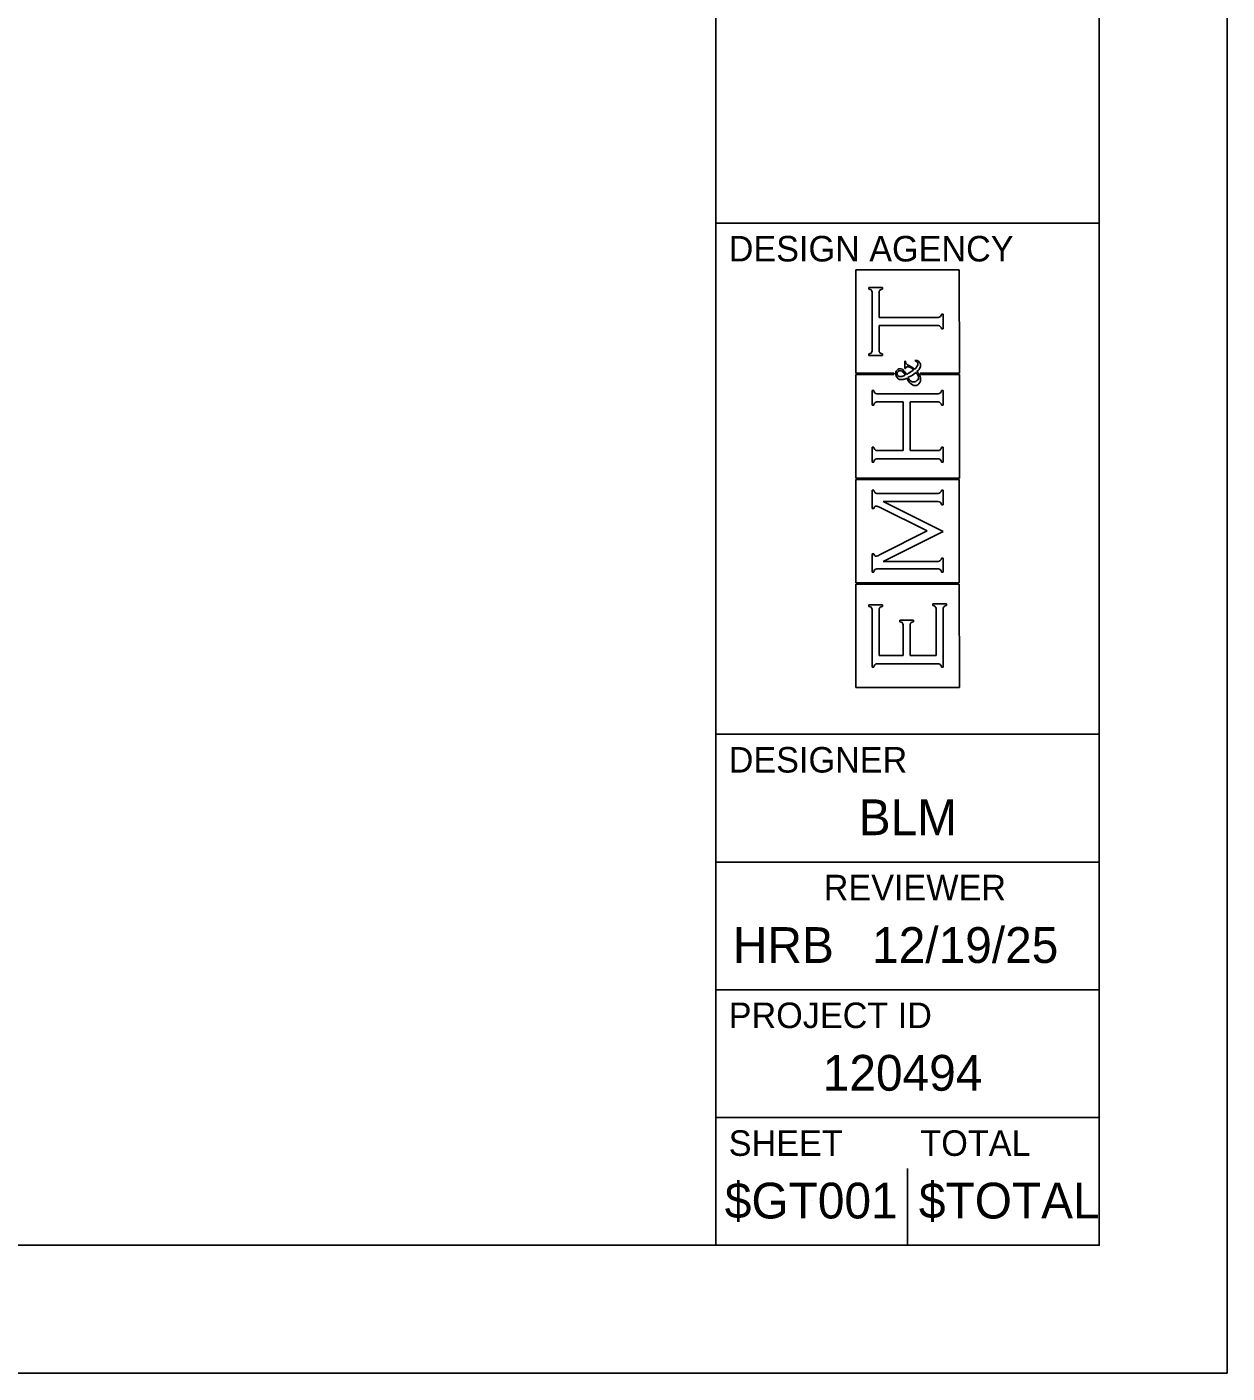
# Model space of a CAD drawing. Extents: x -7.1 to 34, y 0 to 22.
# Drawn here: x 29.3 to 34, y 0 to 5.27 of the extents above; entities that cross this region are included whole.
import ezdxf

# ---------------------------------------------------------------- set-up
doc = ezdxf.new("R2010")
doc.units = 0
for name, color, linetype in [('SH_Border', 7, 'Continuous'), ('SH_Cut_Line', 7, 'Continuous'), ('SH_Data', 7, 'Continuous')]:
    doc.layers.add(name, color=color, linetype=linetype)

msp = doc.modelspace()

# ---------------------------------------------------------------- linework, layer by layer
at = {"layer": 'SH_Border'}
for p, q in [((32, 0.5), (32, 21.5)), ((32, 4.5), (33.5, 4.5)), ((32, 2.5), (33.5, 2.5)), ((32, 2), (33.5, 2)), ((32, 1.5), (33.5, 1.5)), ((32, 1), (33.5, 1))]:
    msp.add_line(p, q, dxfattribs=at)
msp.add_lwpolyline([(1.5, 21.5), (33.5, 21.5), (33.5, 0.5), (1.5, 0.5)], close=True, dxfattribs=at)
at = {"layer": 'SH_Cut_Line'}
msp.add_lwpolyline([(0, 0), (34, 0), (34, 22), (0, 22)], close=True, dxfattribs=at)
at = {"layer": 'SH_Data'}
for p, q in [((32.9523, 4.3174), (32.5477, 4.3174)), ((32.5477, 4.3174), (32.5477, 3.9128)), ((32.9524, 3.9128), (32.9523, 4.3174)), ((32.5984, 4.2421), (32.5984, 4.2486)), ((32.5984, 4.2486), (32.6511, 4.2486)), ((32.6036, 4.2408), (32.5984, 4.2421)), ((32.6071, 4.2391), (32.6036, 4.2408)), ((32.6088, 4.2367), (32.6071, 4.2391)), ((32.6106, 4.2343), (32.6088, 4.2367)), ((32.6114, 4.2303), (32.6106, 4.2343)), ((32.6114, 4.2246), (32.6114, 4.2303)), ((32.6114, 4.0055), (32.6114, 4.2246)), ((32.639, 4.2343), (32.6381, 4.2303)), ((32.6381, 4.2303), (32.6381, 4.2246)), ((32.6381, 4.2246), (32.6381, 4.1309)), ((32.6407, 4.2367), (32.639, 4.2343)), ((32.6424, 4.2391), (32.6407, 4.2367)), ((32.6459, 4.2409), (32.6424, 4.2391)), ((32.6511, 4.2421), (32.6459, 4.2409)), ((32.6511, 4.2486), (32.6511, 4.2421)), ((32.6381, 4.1309), (32.8646, 4.1309)), ((32.8646, 4.1309), (32.8701, 4.1309)), ((32.8701, 4.1309), (32.8741, 4.1318)), ((32.8741, 4.1318), (32.8765, 4.1336)), ((32.8765, 4.1336), (32.8788, 4.1353)), ((32.8788, 4.1353), (32.8807, 4.1388)), ((32.8807, 4.1388), (32.882, 4.1439)), ((32.882, 4.1439), (32.8885, 4.1439)), ((32.8885, 4.1439), (32.8885, 4.0862)), ((32.8646, 4.0992), (32.6381, 4.0992)), ((32.6381, 4.0992), (32.6381, 4.0055)), ((32.8703, 4.0992), (32.8646, 4.0992)), ((32.8743, 4.0983), (32.8703, 4.0992)), ((32.8766, 4.0966), (32.8743, 4.0983)), ((32.8789, 4.0948), (32.8766, 4.0966)), ((32.8807, 4.0914), (32.8789, 4.0948)), ((32.882, 4.0862), (32.8807, 4.0914)), ((32.8885, 4.0862), (32.882, 4.0862)), ((32.6114, 3.9998), (32.6114, 4.0055)), ((32.6381, 4.0055), (32.6381, 3.9998)), ((32.5984, 3.9881), (32.6036, 3.9893)), ((32.5984, 3.9816), (32.5984, 3.9881)), ((32.6511, 3.9816), (32.5984, 3.9816)), ((32.6036, 3.9893), (32.6071, 3.9911)), ((32.6071, 3.9911), (32.6088, 3.9934)), ((32.6088, 3.9934), (32.6106, 3.9958)), ((32.6106, 3.9958), (32.6114, 3.9998)), ((32.6381, 3.9998), (32.639, 3.9958)), ((32.639, 3.9958), (32.6407, 3.9934)), ((32.6407, 3.9934), (32.6424, 3.9911)), ((32.6424, 3.9911), (32.6459, 3.9893)), ((32.6459, 3.9893), (32.6511, 3.9881)), ((32.6511, 3.9881), (32.6511, 3.9816)), ((32.739, 3.9311), (32.739, 3.9596)), ((32.739, 3.9596), (32.7415, 3.9596)), ((32.7415, 3.9596), (32.7418, 3.9556)), ((32.7418, 3.9556), (32.7427, 3.9527)), ((32.7427, 3.9527), (32.7441, 3.9508)), ((32.7794, 3.9612), (32.7813, 3.9637)), ((32.7827, 3.9603), (32.7794, 3.9612)), ((32.7813, 3.9637), (32.7877, 3.9621)), ((32.7852, 3.9588), (32.7827, 3.9603)), ((32.7869, 3.9566), (32.7852, 3.9588)), ((32.7886, 3.9545), (32.7869, 3.9566)), ((32.7877, 3.9621), (32.7924, 3.9594)), ((32.7895, 3.9518), (32.7886, 3.9545)), ((32.7895, 3.9487), (32.7895, 3.9518)), ((32.7924, 3.9594), (32.7955, 3.9557)), ((32.7955, 3.9557), (32.7986, 3.952)), ((32.7986, 3.952), (32.8001, 3.9477)), ((32.5477, 3.9128), (32.6968, 3.9128)), ((32.6963, 3.9073), (32.5477, 3.9073)), ((32.5477, 3.9073), (32.5477, 3.5027)), ((32.6968, 3.9128), (32.6963, 3.9073)), ((32.7041, 3.9168), (32.7057, 3.9211)), ((32.7041, 3.9114), (32.7041, 3.9168)), ((32.7041, 3.9058), (32.7041, 3.9114)), ((32.7057, 3.9007), (32.7041, 3.9058)), ((32.7057, 3.9211), (32.7089, 3.9245)), ((32.7089, 3.8963), (32.7057, 3.9007)), ((32.7089, 3.9245), (32.7121, 3.9279)), ((32.7101, 3.9167), (32.709, 3.9142)), ((32.709, 3.9142), (32.709, 3.9112)), ((32.709, 3.9112), (32.709, 3.9073)), ((32.709, 3.9073), (32.7104, 3.9043)), ((32.7122, 3.9187), (32.7101, 3.9167)), ((32.7104, 3.9043), (32.7131, 3.9023)), ((32.7121, 3.9279), (32.716, 3.9296)), ((32.7143, 3.9207), (32.7122, 3.9187)), ((32.7131, 3.9023), (32.7159, 3.9003)), ((32.717, 3.9217), (32.7143, 3.9207)), ((32.7159, 3.9003), (32.7185, 3.8993)), ((32.716, 3.9296), (32.7206, 3.9296)), ((32.7203, 3.9217), (32.717, 3.9217)), ((32.7185, 3.8993), (32.7212, 3.8993)), ((32.7245, 3.9217), (32.7203, 3.9217)), ((32.7206, 3.9296), (32.7254, 3.9296)), ((32.7212, 3.8993), (32.7234, 3.8993)), ((32.7234, 3.8993), (32.7259, 3.8997)), ((32.7282, 3.9203), (32.7245, 3.9217)), ((32.7254, 3.9296), (32.7296, 3.928)), ((32.7259, 3.8997), (32.7286, 3.9004)), ((32.7316, 3.9175), (32.7282, 3.9203)), ((32.7286, 3.9004), (32.7314, 3.9012)), ((32.7296, 3.928), (32.7332, 3.9247)), ((32.7314, 3.9012), (32.7354, 3.9026)), ((32.735, 3.9147), (32.7316, 3.9175)), ((32.7332, 3.9247), (32.7368, 3.9213)), ((32.7381, 3.9104), (32.735, 3.9147)), ((32.7354, 3.9026), (32.7407, 3.9048)), ((32.7368, 3.9213), (32.7407, 3.9155)), ((32.7407, 3.9048), (32.7381, 3.9104)), ((32.7415, 3.9311), (32.739, 3.9311)), ((32.7407, 3.9155), (32.745, 3.9071)), ((32.7417, 3.9329), (32.7415, 3.9311)), ((32.7424, 3.9343), (32.7417, 3.9329)), ((32.7436, 3.9353), (32.7424, 3.9343)), ((32.7452, 3.9367), (32.7436, 3.9353)), ((32.7441, 3.9508), (32.7455, 3.949)), ((32.745, 3.9071), (32.7551, 3.913)), ((32.7471, 3.9374), (32.7452, 3.9367)), ((32.7455, 3.949), (32.7498, 3.946)), ((32.7491, 3.9374), (32.7471, 3.9374)), ((32.7556, 3.9374), (32.7491, 3.9374)), ((32.7498, 3.946), (32.7569, 3.942)), ((32.7551, 3.913), (32.7645, 3.9191)), ((32.7635, 3.9334), (32.7556, 3.9374)), ((32.7614, 3.9008), (32.7567, 3.8982)), ((32.7569, 3.942), (32.764, 3.938)), ((32.7651, 3.9031), (32.7614, 3.9008)), ((32.773, 3.9253), (32.7635, 3.9334)), ((32.764, 3.938), (32.7707, 3.9335)), ((32.7645, 3.9191), (32.773, 3.9253)), ((32.7688, 3.9054), (32.7651, 3.9031)), ((32.7747, 3.9096), (32.7688, 3.9054)), ((32.7707, 3.9335), (32.7769, 3.9285)), ((32.7828, 3.9155), (32.7747, 3.9096)), ((32.7769, 3.9285), (32.7816, 3.9325)), ((32.7816, 3.9325), (32.7848, 3.9361)), ((32.7866, 3.911), (32.7828, 3.9155)), ((32.7848, 3.9361), (32.7867, 3.9392)), ((32.7891, 3.9074), (32.7866, 3.911)), ((32.7867, 3.9392), (32.7885, 3.9424)), ((32.7916, 3.9236), (32.7867, 3.9191)), ((32.7867, 3.9191), (32.7917, 3.9135)), ((32.7885, 3.9424), (32.7895, 3.9455)), ((32.7902, 3.9048), (32.7891, 3.9074)), ((32.7895, 3.9455), (32.7895, 3.9487)), ((32.7914, 3.9021), (32.7902, 3.9048)), ((32.792, 3.8994), (32.7914, 3.9021)), ((32.795, 3.9277), (32.7916, 3.9236)), ((32.7917, 3.9135), (32.7952, 3.9084)), ((32.792, 3.8965), (32.792, 3.8994)), ((32.797, 3.9315), (32.795, 3.9277)), ((32.7952, 3.9084), (32.7972, 3.9039)), ((32.7991, 3.9353), (32.797, 3.9315)), ((32.7972, 3.9039), (32.7991, 3.8994)), ((32.8001, 3.9391), (32.7991, 3.9353)), ((32.7991, 3.8994), (32.8001, 3.8946)), ((32.8036, 3.9073), (32.7997, 3.9128)), ((32.7997, 3.9128), (32.9524, 3.9128)), ((32.8001, 3.9477), (32.8001, 3.9428)), ((32.8001, 3.9428), (32.8001, 3.9391)), ((32.9524, 3.9073), (32.8036, 3.9073)), ((32.9524, 3.5027), (32.9524, 3.9073)), ((32.7129, 3.8906), (32.7089, 3.8963)), ((32.7188, 3.8878), (32.7129, 3.8906)), ((32.7265, 3.8878), (32.7188, 3.8878)), ((32.7293, 3.8878), (32.7265, 3.8878)), ((32.7322, 3.8881), (32.7293, 3.8878)), ((32.7352, 3.8889), (32.7322, 3.8881)), ((32.7382, 3.8897), (32.7352, 3.8889)), ((32.742, 3.8911), (32.7382, 3.8897)), ((32.7467, 3.8932), (32.742, 3.8911)), ((32.7525, 3.8824), (32.7467, 3.8932)), ((32.7567, 3.8982), (32.7512, 3.8954)), ((32.7512, 3.8954), (32.7543, 3.8901)), ((32.7582, 3.875), (32.7525, 3.8824)), ((32.7543, 3.8901), (32.7578, 3.8861)), ((32.7578, 3.8861), (32.7615, 3.8833)), ((32.7636, 3.8711), (32.7582, 3.875)), ((32.7615, 3.8833), (32.7653, 3.8806)), ((32.769, 3.8672), (32.7636, 3.8711)), ((32.7653, 3.8806), (32.7694, 3.8793)), ((32.7745, 3.8652), (32.769, 3.8672)), ((32.7694, 3.8793), (32.7737, 3.8793)), ((32.7737, 3.8793), (32.7786, 3.8793)), ((32.7799, 3.8652), (32.7745, 3.8652)), ((32.7786, 3.8793), (32.7828, 3.8808)), ((32.7854, 3.8652), (32.7799, 3.8652)), ((32.7828, 3.8808), (32.7865, 3.8839)), ((32.7902, 3.8674), (32.7854, 3.8652)), ((32.7865, 3.8839), (32.7902, 3.8871)), ((32.7902, 3.8871), (32.792, 3.8913)), ((32.7942, 3.8718), (32.7902, 3.8674)), ((32.792, 3.8913), (32.792, 3.8965)), ((32.7981, 3.8762), (32.7942, 3.8718)), ((32.8001, 3.8821), (32.7981, 3.8762)), ((32.8001, 3.8946), (32.8001, 3.8895)), ((32.8001, 3.8895), (32.8001, 3.8821)), ((32.6114, 3.7873), (32.6114, 3.845)), ((32.6114, 3.845), (32.6179, 3.845)), ((32.6179, 3.845), (32.6193, 3.8399)), ((32.621, 3.7959), (32.6192, 3.7924)), ((32.6193, 3.8399), (32.6211, 3.8364)), ((32.6233, 3.7976), (32.621, 3.7959)), ((32.6211, 3.8364), (32.6234, 3.8347)), ((32.6257, 3.7994), (32.6233, 3.7976)), ((32.6234, 3.8347), (32.6257, 3.8329)), ((32.6257, 3.8329), (32.6297, 3.832)), ((32.6297, 3.8003), (32.6257, 3.7994)), ((32.6297, 3.832), (32.6354, 3.832)), ((32.6354, 3.8003), (32.6297, 3.8003)), ((32.6354, 3.832), (32.8646, 3.832)), ((32.7327, 3.8003), (32.6354, 3.8003)), ((32.7327, 3.6098), (32.7327, 3.8003)), ((32.8646, 3.8003), (32.7594, 3.8003)), ((32.7594, 3.8003), (32.7594, 3.6098)), ((32.8646, 3.832), (32.8701, 3.832)), ((32.8703, 3.8003), (32.8646, 3.8003)), ((32.8701, 3.832), (32.8741, 3.8329)), ((32.8743, 3.7994), (32.8703, 3.8003)), ((32.8741, 3.8329), (32.8765, 3.8347)), ((32.8766, 3.7976), (32.8743, 3.7994)), ((32.8765, 3.8347), (32.8788, 3.8364)), ((32.8789, 3.7959), (32.8766, 3.7976)), ((32.8788, 3.8364), (32.8807, 3.8399)), ((32.8807, 3.7924), (32.8789, 3.7959)), ((32.8807, 3.8399), (32.882, 3.845)), ((32.882, 3.845), (32.8885, 3.845)), ((32.8885, 3.845), (32.8885, 3.7873)), ((32.6179, 3.7873), (32.6114, 3.7873)), ((32.6192, 3.7924), (32.6179, 3.7873)), ((32.882, 3.7873), (32.8807, 3.7924)), ((32.8885, 3.7873), (32.882, 3.7873)), ((32.6115, 3.565), (32.6115, 3.6228)), ((32.6115, 3.6228), (32.6179, 3.6228)), ((32.6179, 3.6228), (32.6193, 3.6176)), ((32.6193, 3.6176), (32.6211, 3.6142)), ((32.6211, 3.6142), (32.6234, 3.6124)), ((32.6234, 3.6124), (32.6257, 3.6107)), ((32.6257, 3.6107), (32.6297, 3.6098)), ((32.6297, 3.6098), (32.6354, 3.6098)), ((32.6354, 3.6098), (32.7327, 3.6098)), ((32.7594, 3.6098), (32.8646, 3.6098)), ((32.8646, 3.6098), (32.8703, 3.6098)), ((32.8703, 3.6098), (32.8743, 3.6106)), ((32.8743, 3.6106), (32.8766, 3.6123)), ((32.8766, 3.6123), (32.8789, 3.614)), ((32.8789, 3.614), (32.8807, 3.6175)), ((32.8807, 3.6175), (32.882, 3.6228)), ((32.882, 3.6228), (32.8885, 3.6228)), ((32.8885, 3.6228), (32.8885, 3.565)), ((32.6179, 3.565), (32.6115, 3.565)), ((32.6192, 3.5702), (32.6179, 3.565)), ((32.621, 3.5736), (32.6192, 3.5702)), ((32.6233, 3.5754), (32.621, 3.5736)), ((32.6257, 3.5771), (32.6233, 3.5754)), ((32.6297, 3.578), (32.6257, 3.5771)), ((32.6354, 3.578), (32.6297, 3.578)), ((32.8646, 3.578), (32.6354, 3.578)), ((32.8703, 3.578), (32.8646, 3.578)), ((32.8743, 3.5772), (32.8703, 3.578)), ((32.8766, 3.5755), (32.8743, 3.5772)), ((32.8789, 3.5738), (32.8766, 3.5755)), ((32.8807, 3.5703), (32.8789, 3.5738)), ((32.882, 3.565), (32.8807, 3.5703)), ((32.8885, 3.565), (32.882, 3.565)), ((32.5477, 3.5027), (32.9524, 3.5027)), ((32.9523, 3.4973), (32.5477, 3.4973)), ((32.5477, 3.4973), (32.5477, 3.0927)), ((32.75, 3.5), (32.75, 3.5)), ((32.9523, 3.0927), (32.9523, 3.4973)), ((32.6115, 3.3831), (32.6115, 3.4555)), ((32.6115, 3.4555), (32.6179, 3.4555)), ((32.6179, 3.4555), (32.6193, 3.4504)), ((32.6193, 3.4504), (32.6211, 3.4469)), ((32.6211, 3.4469), (32.6234, 3.4452)), ((32.6234, 3.4452), (32.6257, 3.4434)), ((32.6257, 3.4434), (32.6297, 3.4425)), ((32.6297, 3.4425), (32.6354, 3.4425)), ((32.6354, 3.4425), (32.8646, 3.4425)), ((32.8646, 3.4425), (32.8701, 3.4425)), ((32.8701, 3.4425), (32.8741, 3.4434)), ((32.8741, 3.4434), (32.8765, 3.4452)), ((32.8765, 3.4452), (32.8788, 3.4469)), ((32.8788, 3.4469), (32.8807, 3.4504)), ((32.8807, 3.4504), (32.882, 3.4555)), ((32.882, 3.4555), (32.8885, 3.4555)), ((32.8885, 3.4555), (32.8885, 3.3978)), ((32.6179, 3.3831), (32.6115, 3.3831)), ((32.6202, 3.3897), (32.6179, 3.3831)), ((32.6232, 3.3931), (32.6202, 3.3897)), ((32.6267, 3.3931), (32.6232, 3.3931)), ((32.6294, 3.3931), (32.6267, 3.3931)), ((32.634, 3.3914), (32.6294, 3.3931)), ((32.6405, 3.3882), (32.634, 3.3914)), ((32.8259, 3.2954), (32.6405, 3.3882)), ((32.8645, 3.4108), (32.6549, 3.4108)), ((32.6549, 3.4108), (32.8885, 3.2928)), ((32.8702, 3.4108), (32.8645, 3.4108)), ((32.8742, 3.4099), (32.8702, 3.4108)), ((32.8765, 3.4082), (32.8742, 3.4099)), ((32.8789, 3.4066), (32.8765, 3.4082)), ((32.8807, 3.4031), (32.8789, 3.4066)), ((32.882, 3.3978), (32.8807, 3.4031)), ((32.8885, 3.3978), (32.882, 3.3978)), ((32.6421, 3.2029), (32.8259, 3.2954)), ((32.8885, 3.2928), (32.6549, 3.1763)), ((32.6115, 3.1344), (32.6115, 3.2062)), ((32.6115, 3.2062), (32.6179, 3.2062)), ((32.6179, 3.2062), (32.6202, 3.1996)), ((32.6202, 3.1996), (32.6231, 3.1962)), ((32.6231, 3.1962), (32.6265, 3.1962)), ((32.6265, 3.1962), (32.6281, 3.1962)), ((32.6281, 3.1962), (32.6333, 3.1985)), ((32.6333, 3.1985), (32.6421, 3.2029)), ((32.6549, 3.1763), (32.8645, 3.1763)), ((32.8645, 3.1763), (32.8701, 3.1763)), ((32.8701, 3.1763), (32.8741, 3.1772)), ((32.8741, 3.1772), (32.8764, 3.1789)), ((32.8764, 3.1789), (32.8788, 3.1807)), ((32.8788, 3.1807), (32.8807, 3.1841)), ((32.8807, 3.1841), (32.882, 3.1893)), ((32.882, 3.1893), (32.8885, 3.1893)), ((32.8885, 3.1893), (32.8885, 3.1344)), ((32.6179, 3.1344), (32.6115, 3.1344)), ((32.6192, 3.1396), (32.6179, 3.1344)), ((32.621, 3.143), (32.6192, 3.1396)), ((32.6233, 3.1448), (32.621, 3.143)), ((32.6257, 3.1465), (32.6233, 3.1448)), ((32.6297, 3.1474), (32.6257, 3.1465)), ((32.6354, 3.1474), (32.6297, 3.1474)), ((32.8646, 3.1474), (32.6354, 3.1474)), ((32.8703, 3.1474), (32.8646, 3.1474)), ((32.8743, 3.1465), (32.8703, 3.1474)), ((32.8766, 3.1448), (32.8743, 3.1465)), ((32.8789, 3.143), (32.8766, 3.1448)), ((32.8807, 3.1396), (32.8789, 3.143)), ((32.882, 3.1344), (32.8807, 3.1396)), ((32.8885, 3.1344), (32.882, 3.1344)), ((32.5477, 3.0927), (32.9523, 3.0927)), ((32.9523, 3.0872), (32.5477, 3.0872)), ((32.5477, 3.0872), (32.5477, 2.6826)), ((32.9524, 2.6826), (32.9523, 3.0872)), ((32.5985, 3.0004), (32.5985, 3.0069)), ((32.5985, 3.0069), (32.6512, 3.0069)), ((32.6512, 3.0069), (32.6512, 3.0004)), ((32.8489, 3.0033), (32.8489, 3.0097)), ((32.8489, 3.0097), (32.9016, 3.0097)), ((32.854, 3.002), (32.8489, 3.0033)), ((32.9016, 3.0033), (32.8964, 3.0019)), ((32.9016, 3.0097), (32.9016, 3.0033)), ((32.6037, 2.999), (32.5985, 3.0004)), ((32.6071, 2.9972), (32.6037, 2.999)), ((32.6089, 2.9949), (32.6071, 2.9972)), ((32.6106, 2.9926), (32.6089, 2.9949)), ((32.6115, 2.9886), (32.6106, 2.9926)), ((32.6115, 2.9829), (32.6115, 2.9886)), ((32.6115, 2.763), (32.6115, 2.9829)), ((32.6391, 2.9926), (32.6382, 2.9886)), ((32.6382, 2.9886), (32.6382, 2.9829)), ((32.6382, 2.9829), (32.6382, 2.8077)), ((32.6409, 2.995), (32.6391, 2.9926)), ((32.6426, 2.9973), (32.6409, 2.995)), ((32.6461, 2.9991), (32.6426, 2.9973)), ((32.6512, 3.0004), (32.6461, 2.9991)), ((32.8575, 3.0002), (32.854, 3.002)), ((32.8592, 2.9979), (32.8575, 3.0002)), ((32.861, 2.9955), (32.8592, 2.9979)), ((32.8619, 2.9914), (32.861, 2.9955)), ((32.8619, 2.9858), (32.8619, 2.9914)), ((32.8619, 2.8077), (32.8619, 2.9858)), ((32.8894, 2.9953), (32.8886, 2.9913)), ((32.8886, 2.9913), (32.8886, 2.9856)), ((32.8886, 2.9856), (32.8886, 2.763)), ((32.8912, 2.9977), (32.8894, 2.9953)), ((32.893, 3), (32.8912, 2.9977)), ((32.8964, 3.0019), (32.893, 3)), ((32.7197, 2.9398), (32.7197, 2.9462)), ((32.7197, 2.9462), (32.7724, 2.9462)), ((32.7249, 2.9385), (32.7197, 2.9398)), ((32.7283, 2.9367), (32.7249, 2.9385)), ((32.7301, 2.9344), (32.7283, 2.9367)), ((32.7318, 2.932), (32.7301, 2.9344)), ((32.7327, 2.928), (32.7318, 2.932)), ((32.7327, 2.9223), (32.7327, 2.928)), ((32.7327, 2.8077), (32.7327, 2.9223)), ((32.7603, 2.932), (32.7594, 2.928)), ((32.7594, 2.928), (32.7594, 2.9223)), ((32.7594, 2.9223), (32.7594, 2.8077)), ((32.762, 2.9344), (32.7603, 2.932)), ((32.7638, 2.9367), (32.762, 2.9344)), ((32.7672, 2.9385), (32.7638, 2.9367)), ((32.7724, 2.9398), (32.7672, 2.9385)), ((32.7724, 2.9462), (32.7724, 2.9398)), ((32.6382, 2.8077), (32.7327, 2.8077)), ((32.7594, 2.8077), (32.8619, 2.8077)), ((32.618, 2.763), (32.6115, 2.763)), ((32.6193, 2.7681), (32.618, 2.763)), ((32.6212, 2.7716), (32.6193, 2.7681)), ((32.6235, 2.7733), (32.6212, 2.7716)), ((32.6258, 2.7751), (32.6235, 2.7733)), ((32.6297, 2.776), (32.6258, 2.7751)), ((32.6354, 2.776), (32.6297, 2.776)), ((32.8646, 2.776), (32.6354, 2.776)), ((32.8703, 2.776), (32.8646, 2.776)), ((32.8743, 2.7751), (32.8703, 2.776)), ((32.8766, 2.7734), (32.8743, 2.7751)), ((32.8789, 2.7717), (32.8766, 2.7734)), ((32.8807, 2.7682), (32.8789, 2.7717)), ((32.8821, 2.763), (32.8807, 2.7682)), ((32.8886, 2.763), (32.8821, 2.763)), ((32.5477, 2.6826), (32.9524, 2.6826)), ((32.75, 0.5), (32.75, 0.8)), ((32.375, 0.675), (32.375, 0.675))]:
    msp.add_line(p, q, dxfattribs=at)

# ---------------------------------------------------------------- texts
for s, height, p in [('DESIGN AGENCY', 0.1, (32.05, 4.35)), ('DESIGNER', 0.1, (32.05, 2.35)), ('BLM', 0.14, (32.5586, 2.105)), ('REVIEWER', 0.1, (32.4218, 1.85)), ('HRB', 0.14, (32.0662, 1.605)), ('12/19/25', 0.14, (32.611, 1.605)), ('PROJECT ID', 0.1, (32.05, 1.35)), ('120494', 0.14, (32.4179, 1.105)), ('SHEET', 0.1, (32.05, 0.85)), ('TOTAL', 0.1, (32.8, 0.85)), ('$GT001', 0.14, (32.0347, 0.605)), ('$TOTAL', 0.14, (32.7941, 0.605))]:
    msp.add_text(s, height=height, dxfattribs=at).set_placement(p)

doc.saveas('drawing.dxf')
